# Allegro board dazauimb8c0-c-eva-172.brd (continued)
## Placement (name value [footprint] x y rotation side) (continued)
R242  0_5%_2  [R0201]  64.5 45.96 180 top
R243  75K_1%_2  [R0201]  61.28 45.83 0 top
R244  *EV@10K_5%_4  [R0402]  63.05 45.45 0 top
R245  EV@100K_5%_4  [R0402]  65.97 45.4 0 top
R246  TPC@0_5%_2  [R0201]  20.25 45.33 90 top
R247  TPC@0_5%_2  [R0201]  21.52 45.33 90 top
R248  4.7K_5%_2  [R0201]  213.57 45.27 90 top
R249  *10K_5%_4  [R0402]  215.38 45.22 180 top
R250  *10K_1%_2  [R0201]  78.37 45 0 top
R251  TPC_N@0_5%_2  [R0201]  20.25 44.87 270 top
R252  TPC_N@0_5%_2  [R0201]  21.52 44.87 270 top
R253  *10K_5%_2  [R0201]  60.69 44.87 90 top
R254  0_5%_2  [R0201]  63.43 44.54 180 top
R255  *1K_5%_2  [R0201]  81.72 44.06 90 top
R256  *10K_5%_2  [R0201]  78.04 43.93 180 top
R257  2.2K_5%_2  [R0201]  213.57 43.93 0 top
R258  *10K_1%_2  [R0201]  62.11 43.67 90 top
R259  200_1%_2  [R0201]  80.96 43.67 90 top
R260  2.2K_5%_2  [R0201]  213.57 42.91 0 top
R261  EV@10K_5%_4  [R0402]  62.14 42.23 90 top
R262  *EV@10K_5%_4  [R0402]  66.36 42.2 270 top
R263  *0_5%_4  [R0402]  97.06 42.02 0 top
R264  0_5%_4  [R0402]  30.54 41.9 90 top
R265  *0_5%_2  [R0201]  107.66 41.85 180 top
R266  *100K_5%_2  [R0201]  65.8 40.93 180 top
R267  *0_5%_4  [R0402]  30.16 40.5 180 top
R268  0_5%_4  [R0402]  97.98 40.25 180 top
R269  *100K_5%_2  [R0201]  65.21 40.12 180 top
R270  0_5%_2  [R0201]  61.78 39.48 270 top
R271  0_5%_2  [R0201]  62.55 39.48 270 top
R272  10K_5%_2  [R0201]  65.21 39.36 0 top
R273  *0_5%_4  [R0402]  97.34 39.23 0 top
R274  0_5%_8  [R0805]  101.66 39.03 90 top
R275  *0_5%_4  [R0402]  210.63 38.85 180 top
R276  10K_5%_2  [R0201]  65.21 38.59 0 top
R277  *100K_1%_2  [R0201]  93.2 38.29 0 top
R278  470_1%_2  [R0201]  66.36 38.09 0 top
R279  0_5%_4  [R0402]  97.09 38.09 0 top
R280  *Short_0402  [S0402]  22.67 37.96 180 top
R281  *short_4  [S0402]  210.63 37.83 180 top
R282  0_5%_2  [R0201]  66.48 37.2 270 top
R283  0_5%_4  [R0402]  97.1 37.11 0 top
R284  *Short_0402  [S0402]  22.67 36.94 180 top
R285  113_1%_2  [R0201]  95.69 36.56 180 top
R286  10K_5%_2  [R0201]  100.52 36.5 90 top
R287  10K_5%_2  [R0201]  93.23 36.44 180 top
R288  *0_5%_2  [R0201]  107.12 36.31 180 top
R289  *0_5%_4  [R0402]  210.75 35.8 180 top
R290  *20K_1%_2  [R0201]  90.49 35.72 90 top
R291  100K_5%_2  [R0201]  66.38 34.53 0 top
R292  100_1%_2  [R0201]  100.52 35.36 90 top
R293  *Short_0402  [S0402]  22.03 35.17 180 top
R294  240_1%_2  [R0201]  39.85 34.91 180 top
R295  0_5%_4  [R0402]  41.46 34.91 180 top
R296  49.9_1%_2  [R0201]  96.33 34.78 180 top
R297  *0_5%_2  [R0201]  107 34.73 270 top
R298  *Short_0402  [S0402]  22.03 34.15 180 top
R299  10K_5%_2  [R0201]  92.87 34.02 180 top
R300  1K_5%_2  [R0201]  93.91 34.02 0 top
R301  20K_1%_2  [R0201]  97.09 34.02 0 top
R302  75K_1%_2  [R0201]  87.06 33.64 180 top
R303  *20K_1%_2  [R0201]  88.43 33.44 90 top
R304  *4.7K_5%_2  [R0201]  97.09 33.26 180 top
R305  *Short_0402  [S0402]  22.16 33.13 180 top
R306  10K_5%_4  [R0402]  93.15 33.01 0 top
R307  22_1%_2  [R0201]  86.24 32.75 270 top
R308  60.4_1%_2  [R0201]  95.44 32.63 180 top
R309  *10K_1%_2  [R0201]  182.69 32.37 0 top
R310  33_5%_2  [R0201]  183.7 32.37 0 top
R311  75K_1%_2  [R0201]  85.53 32.32 270 top
R312  22_1%_4  [R0402]  158.99 32.32 0 top
R313  256@0_5%_4  [R0402]  213.12 32.29 0 top
R314  4.7K_5%_2  [R0201]  189.98 32.24 90 top
R315  4.7K_5%_2  [R0201]  190.71 32.24 90 top
R316  *Short_0402  [S0402]  22.16 32.12 180 top
R317  10K_5%_2  [R0201]  66.36 32.14 180 top
R318  33_5%_2  [R0201]  197.06 32.12 90 top
R319  75_1%_4  [R0402]  192.31 31.86 90 top
R320  75_1%_4  [R0402]  193.28 31.86 90 top
R321  75_1%_4  [R0402]  194.24 31.86 90 top
R322  0_5%_4  [R0402]  195.21 31.86 90 top
R323  22_1%_4  [R0402]  161.22 31.61 180 top
R324  100K_1%_4  [R0402]  162.98 31.61 0 top
R325  *10K_1%_2  [R0201]  181.42 31.53 90 top
R326  200_1%_2  [R0201]  84.77 31.48 270 top
R327  *10K_1%_2  [R0201]  94.3 31.36 0 top
R328  *4.7K_5%_2  [R0201]  85.84 31.33 90 top
R329  22_1%_2  [R0201]  87.11 31.3 270 top
R330  *10K_5%_2  [R0201]  66.31 30.92 180 top
R331  *0_5%_4  [R0402]  179.11 31.2 90 top
R332  *22_5%_8  [R0805]  51.4 31.13 90 top
R333  10K_1%_2  [R0201]  180.12 31.1 180 top
R334  20K_1%_2  [R0201]  89.77 30.8 180 top
R335  22_1%_4  [R0402]  161.99 30.59 0 top
R336  *short_4  [S0402]  167.45 30.59 180 top
R337  *20K_1%_2  [R0201]  86.68 30.39 180 top
R338  *256@0_5%_4  [R0402]  208.67 30.24 90 top
R339  100K_5%_2  [R0201]  66 29.15 0 top
R340  EV@4.7K_5%_2  [R0201]  171.36 30.19 0 top
R341  EV@4.7K_5%_2  [R0201]  173.11 30.19 180 top
R342  10K_5%_4  [R0402]  84.82 30.11 90 top
R343  100K_5%_4  [R0402]  95.57 29.96 0 top
R344  *short_4  [S0402]  180.15 29.83 270 top
R345  *short_4  [S0402]  202.02 29.83 135 top
R346  4.7K_5%_2  [R0201]  89.47 29.81 90 top
R347  *4.7K_5%_2  [R0201]  90.18 29.81 90 top
R348  100K_5%_2  [R0201]  181.04 29.73 270 top
R349  0_5%_2  [R0201]  146.11 29.7 270 top
R350  CNV@75K_1%_2  [R0201]  147.22 29.7 0 top
R351  100K_1%_4  [R0402]  164.15 29.65 0 top
R352  *866_1%_4  [R0402]  49.46 29.45 180 top
R353  *4.7K_5%_2  [R0201]  86.93 29.45 90 top
R354  43_5%_2  [R0201]  179.11 29.3 90 top
R355  *10K_5%_4  [R0402]  210.65 29.3 180 top
R356  2.2K_5%_2  [R0201]  91.78 29.27 180 top
R357  2.2K_5%_2  [R0201]  92.77 29.27 0 top
R358  0_5%_6  [R0603]  161.96 29.15 180 top
R359  100K_5%_2  [R0201]  65.75 28.41 0 top
R360  256@100K_5%_4  [R0402]  200.72 28.99 90 top
R361  2.2K_5%_2  [R0201]  89.98 28.94 180 top
R362  10K_1%_2  [R0201]  170.98 28.89 0 top
R363  22_1%_4  [R0402]  164.15 28.69 0 top
R364  1K_5%_2  [R0201]  210.65 28.28 0 top
R365  1K_5%_2  [R0201]  173.92 28.26 180 top
R366  *255@0_5%_4  [R0402]  209.31 28.21 270 top
R367  2.2K_5%_2  [R0201]  89.98 28.18 180 top
R368  33_5%_2  [R0201]  180.91 28.18 270 top
R369  10K_5%_4  [R0402]  171.89 28.05 180 top
R370  10K_5%_4  [R0402]  175.83 27.93 180 top
R371  10K_5%_4  [R0402]  177.61 27.93 0 top
R372  0_5%_2  [R0201]  65.34 27.55 270 top
R373  *0_5%_4  [R0402]  202.63 27.52 90 top
R374  *short_4  [S0402]  204.96 27.52 90 top
R375  *Short_0402  [S0402]  206.36 27.37 180 top
R376  SP@10K_5%_4  [R0402]  87.18 27.16 0 top
R377  10K_5%_4  [R0402]  79.97 26.78 90 top
R378  10K_1%_2  [R0201]  92.62 26.48 270 top
R379  *0_5%_2  [R0201]  89.85 26.4 90 top
R380  0_5%_2  [R0201]  90.61 26.4 90 top
R381  0_5%_2  [R0201]  91.37 26.4 90 top
R382  22_1%_4  [R0402]  162.62 26.4 180 top
R383  *10K_5%_2  [R0201]  88.96 26.38 270 top
R384  0_5%_4  [R0402]  164.78 26.38 180 top
R385  SP@10K_5%_4  [R0402]  85.6 26.35 270 top
R386  *2M_1%_4  [R0402]  47.94 25.77 0 top
R387  *1M_5%_4  [R0402]  49.72 25.77 0 top
R388  EV@100K_1%_4  [R0402]  78.7 25.77 270 top
R389  SP@10K_5%_4  [R0402]  86.96 25.54 0 top
R390  10K_5%_4  [R0402]  81.98 25.26 90 top
R391  *10K_5%_4  [R0402]  82.94 25.26 90 top
R392  SP@10K_5%_4  [R0402]  83.91 25.26 90 top
R393  33_5%_2  [R0201]  202.12 25.16 90 top
R394  33_5%_2  [R0201]  79.67 24.88 90 top
R395  33_5%_2  [R0201]  80.38 24.88 90 top
R396  *CNV@75K_1%_2  [R0201]  146.96 24.88 0 top
R397  8.2K_1%_2  [R0201]  66.61 24.78 180 top
R398  *TPM@Short_0201  [S0201]  122.87 24.5 270 top
R399  100K_5%_4  [R0402]  175.88 24.24 90 top
R400  *TPM@Short_0201  [S0201]  121.35 23.99 270 top
R401  2.2_5%_6  [R0603]  174.66 23.86 90 top
R402  33_5%_2  [R0201]  203.9 23.79 270 top
R403  TPM@33_5%_2  [R0201]  120.41 23.61 0 top
R404  CNV@75K_1%_2  [R0201]  147.64 23.61 180 top
R405  *20K_1%_2  [R0201]  67.24 23.48 180 top
R406  200K_1%_2  [R0201]  68.24 23.48 0 top
R407  TPC@100K_5%_4  [R0402]  205.67 23.48 270 top
R408  *20K_1%_2  [R0201]  77.15 23.1 0 top
R409  IV@1K/F_4  [R0402]  78.67 22.95 270 top
R410  33_5%_2  [R0201]  202.93 22.8 270 top
R411  TPM@10K_1%_2  [R0201]  120.66 22.69 270 top
R412  *TPM@Short_0201  [S0201]  121.4 22.69 270 top
R413  *4.7K_5%_2  [R0201]  67.88 22.59 90 top
R414  10K_5%_4  [R0402]  74.36 22.29 90 top
R415  *2.2K_5%_2  [R0201]  77.05 22.08 90 top
R416  *Short_0201  [S0201]  200.47 21.96 0 top
R417  TPM@33_5%_2  [R0201]  121.3 21.84 0 top
R418  PBA@10K_5%_4  [R0402]  51.9 21.83 270 top
R419  *22_5%_4  [R0402]  178.65 21.7 90 top
R420  *TPM@Short_0603  [S0603]  132.65 21.58 90 top
R421  TPC_N@100K_5%_4  [R0402]  204.35 21.58 270 top
R422  *Short_0402  [S0402]  47.31 21.32 180 top
R423  *TPM@1.2K_5%_2  [R0201]  130.34 20.56 180 top
R424  *10K_5%_4  [R0402]  70.65 20.46 180 top
R425  HDD_N@0_5%_2  [R0201]  209.1 20.38 90 top
R426  HDD_N@0_5%_2  [R0201]  210.37 20.38 90 top
R427  HDD_N@0_5%_2  [R0201]  211.14 20.38 90 top
R428  HDD_N@0_5%_2  [R0201]  212.51 20.38 90 top
R429  4.7K_5%_2  [R0201]  72.45 19.93 0 top
R430  33_5%_2  [R0201]  149.54 19.93 90 top
R431  *GS@Short_0402  [S0402]  58.48 19.67 180 top
R432  *TPM@0_5%_6  [R0603]  132.27 19.54 180 top
R433  *Short_0402  [S0402]  70.65 19.44 180 top
R434  *10K_5%_4  [R0402]  74.74 19.04 0 top
R435  HDD_R@4.7K_5%_2  [R0201]  205.04 18.91 180 top
R436  *HDD_R@4.7K_5%_2  [R0201]  206.82 18.88 0 top
R437  *0_5%_4  [R0402]  70.65 18.48 0 top
R438  *PBA@0_5%_4  [R0402]  47.43 18.4 90 top
R439  *CNV@71.5K_1%_4  [R0402]  145.71 18.15 180 top
R440  100K_5%_4  [R0402]  177.61 18.15 90 top
R441  *Short_0201  [S0201]  179.87 18.15 0 top
R442  *Short_0603  [S0603]  114.54 17.97 270 top
R443  *Short_0603  [S0603]  116.01 17.97 270 top
R444  *Short_0603  [S0603]  117.44 17.97 270 top
R445  *Short_0603  [S0603]  118.86 17.97 270 top
R446  *HDD_R@4.7K_5%_2  [R0201]  206.82 17.77 0 top
R447  TPC@10K_1%_4  [R0402]  21.37 17.69 270 top
R448  TPM@10K_1%_2  [R0201]  121.42 17.66 0 top
R449  *Short_0402  [S0402]  74.97 17.64 90 top
R450  *0_5%_4  [R0402]  75.93 17.64 270 top
R451  HDD_R@4.7K_5%_2  [R0201]  204.53 17.64 180 top
R452  *TPM@0_5%_6  [R0603]  131.94 17.51 270 top
R453  *TPM@Short_0603  [S0603]  134.25 17.51 270 top
R454  *10K_1%_4  [R0402]  54.8 17.39 270 top
R455  0_5%_2  [R0201]  146.32 17.28 0 top
R456  *0_5%_2  [R0201]  55.69 17 270 top
R457  *Short_0201  [S0201]  56.45 17 270 top
R458  TPM@33_5%_2  [R0201]  121.42 16.95 0 top
R459  100K_5%_2  [R0201]  201.41 16.95 0 top
R460  HDD_R@4.7K_5%_2  [R0201]  206.82 16.75 0 top
R461  *HDD_R@4.7K_5%_2  [R0201]  204.53 16.67 180 top
R462  100K_5%_2  [R0201]  180.55 16.37 270 top
R463  ODD@10K_5%_4  [R0402]  127.05 16.29 0 top
R464  *short_4  [S0402]  69.15 16.24 90 top
R465  *HDD_R@4.7K_5%_2  [R0201]  204.53 15.71 180 top
R466  HDD_R@4.7K_5%_2  [R0201]  206.82 15.61 0 top
R467  *0_5%_2  [R0201]  57.21 15.23 270 top
R468  *GS@10K_1%_2  [R0201]  69.15 14.97 180 top
R469  4.7K_5%_2  [R0201]  72.6 14.77 0 top
R470  *HDD_R@4.7K_5%_2  [R0201]  204.53 14.74 180 top
R471  HDD_R@4.7K_5%_2  [R0201]  206.82 14.72 0 top
R472  TPC@422K_1%_4  [R0402]  15.4 14.34 90 top
R473  0_5%_2  [R0201]  57.34 14.34 0 top
R474  *100K_2  [R0201]  53.96 14.26 90 top
R475  *GS@Short_0201  [S0201]  69.15 14.21 180 top
R476  *HDD_R@4.7K_5%_2  [R0201]  204.53 13.78 180 top
R477  HDD_R@4.7K_5%_2  [R0201]  206.79 13.32 0 top
R478  TPC@10K_1%_4  [R0402]  26.22 13.03 90 top
R479  EV@10K_1%_4  [R0402]  200.47 12.94 180 top
R480  *EV@10K_1%_4  [R0402]  202.37 12.94 180 top
R481  HDD_R@4.7K_5%_2  [R0201]  204.53 12.81 180 top
R482  TPC@100K_1%_4  [R0402]  17.03 12.61 0 top
R483  *GS@10K_1%_2  [R0201]  65.47 12.56 90 top
R484  *GS@Short_0201  [S0201]  66.36 12.56 90 top
R485  *HDD_R@4.7K_5%_2  [R0201]  206.79 12.56 0 top
R486  *TPC@Short_0402  [S0402]  10.6 11.8 180 top
R487  33_5%_2  [R0201]  197.55 11.67 180 top
R488  *HDD_R@Short_0402  [S0402]  204.91 11.16 90 top
R489  *TPC@Short_0402  [S0402]  10.6 10.65 180 top
R490  TPC@100K_1%_4  [R0402]  16.7 10.15 90 top
R491  *SSD@0_5%_2  [R0201]  22.29 9.26 0 top
R492  SSD@100K_1%_4  [R0402]  22.29 8.24 180 top
R493  TPC@470_1%_6  [R0603]  12.33 8.06 0 top
R494  TPC@10K_1%_4  [R0402]  14.13 7.78 90 top
R495  *SSD@Short_0201  [S0201]  26.73 6.59 180 top
R496  100K_1%_4  [R0402]  15.43 5.96 0 top
R497  *SSD@Short_0201  [S0201]  28.76 3.54 0 top
R498  *SSD@Short_0201  [S0201]  31.43 3.54 0 top
R499  *short_4  [S0402]  13.02 3.42 0 top
R500  *SSD@Short_0805  [S0805]  24.95 3.03 180 top
R501  *SSD@100K_5%_4  [R0402]  31.43 2.65 180 top
R502  *short_4  [S0402]  102.25 125.49 0 bottom
R503  EV@100K_1%_4  [R0402]  100.26 124.32 180 bottom
R504  EV@100K_1%_4  [R0402]  102.78 124.14 90 bottom
R505  *EV@Short_0402  [S0402]  104.33 123.43 180 bottom
R506  *EV@Short_0402  [S0402]  100.26 123.3 0 bottom
R507  2.2_5%_6  [R0603]  42.86 121.02 0 bottom
R508  EV@10K_1%_4  [R0402]  95.06 119.24 180 bottom
R509  *EV@Short_0402  [S0402]  100.77 119.24 180 bottom
R510  *EV@0_5%_4  [R0402]  100.77 118.22 180 bottom
R511  EV@2.49K_1%_2  [R0201]  116.65 118.06 270 bottom
R512  *EV@200_1%_2  [R0201]  115.25 117.84 180 bottom
R513  EV@10K_1%_4  [R0402]  103.34 117.82 180 bottom
R514  *Short_0402  [S0402]  40.07 115.68 180 bottom
R515  *Short_0805  [S0805]  67.63 108.77 90 bottom
R516  33_5%_2  [R0201]  58.05 105.17 90 bottom
R517  33_5%_2  [R0201]  56.2 105.04 180 bottom
R518  *Short_0603  [S0603]  59.12 104.76 270 bottom
R519  *Short_0402  [S0402]  44.13 103.62 90 bottom
R520  *Short_0402  [S0402]  45.15 103.62 90 bottom
R521  *Short_0402  [S0402]  46.16 103.62 90 bottom
R522  *Short_0402  [S0402]  47.18 103.62 90 bottom
R523  EV@120_1%_2  [R0201]  132.56 102.35 0 bottom
R524  EV@80.6_1%_2  [R0201]  134.17 102.35 180 bottom
R525  EV@10K_1%_4  [R0402]  119.31 100.82 270 bottom
R526  EV@10K_1%_4  [R0402]  119.31 98.92 270 bottom
R527  EV@10K_1%_4  [R0402]  121.22 98.92 0 bottom
R528  EV@10K_1%_4  [R0402]  90.49 98.16 0 bottom
R529  *EV@100K_5%_4  [R0402]  88.2 97.65 0 bottom
R530  EV@120_1%_2  [R0201]  132.78 97.48 270 bottom
R531  EV@80.6_1%_2  [R0201]  134.94 97.27 180 bottom
R532  EV@100K_5%_4  [R0402]  90.49 97.14 180 bottom
R533  EV@100K_5%_4  [R0402]  88.2 96.63 0 bottom
R534  EV@100K_5%_4  [R0402]  90.49 96.13 180 bottom
R535  100K_1%_2  [R0201]  81 96.02 0 bottom
R536  *short_4  [S0402]  82.61 96.02 180 bottom
R537  EV@10K_1%_4  [R0402]  85.13 95.77 270 bottom
R538  EV@100K_5%_4  [R0402]  88.2 95.62 0 bottom
R539  EV@100K_5%_4  [R0402]  90.49 94.98 0 bottom
R540  *EV@100K_5%_4  [R0402]  88.2 94.6 0 bottom
R541  EV@60.4_1%_2  [R0201]  120.48 94.47 0 bottom
R542  *EV@0_5%_4  [R0402]  85.13 94.09 0 bottom
R543  EV@100K_5%_4  [R0402]  90.49 93.97 180 bottom
R544  EV@100K_5%_4  [R0402]  88.2 93.59 0 bottom
R545  EV@100K_5%_4  [R0402]  90.49 92.95 180 bottom
R546  *EV@100K_5%_4  [R0402]  88.2 92.57 0 bottom
R547  EV@100K_5%_4  [R0402]  90.49 91.93 180 bottom
R548  EV@10K_1%_4  [R0402]  88.2 91.55 0 bottom
R549  *EV@Short_0402  [S0402]  90.23 90.92 180 bottom
R550  EV@10K_1%_4  [R0402]  87.95 90.56 0 bottom
R551  *EV@Short_0402  [S0402]  90.23 89.95 180 bottom
R552  EV@100K_5%_4  [R0402]  103.69 89.78 180 bottom
R553  *EV@30.1K_1%_4  [R0402]  105.47 89.78 0 bottom
R554  *EV@100K_5%_4  [R0402]  107.25 89.78 180 bottom
R555  *EV@10K_1%_4  [R0402]  88.2 89.52 0 bottom
R556  EV@10K_5%_4  [R0402]  91.6 89.01 90 bottom
R557  *EV@10K_5%_4  [R0402]  92.57 89.01 90 bottom
R558  EV@2.2K_5%_2  [R0201]  93.53 89.01 270 bottom
R559  EV@2.2K_5%_2  [R0201]  94.5 89.01 270 bottom
R560  EV@2.2K_5%_2  [R0201]  95.46 89.01 270 bottom
R561  EV@2.2K_5%_2  [R0201]  96.43 89.01 270 bottom
R562  *EV@10K_1%_4  [R0402]  97.39 89.01 90 bottom
R563  EV@10K_1%_4  [R0402]  98.36 89.01 90 bottom
R564  EV@10K_1%_4  [R0402]  90.23 88.99 0 bottom
R565  EV@100K_5%_4  [R0402]  103.69 88.81 0 bottom
R566  EV@100K_5%_4  [R0402]  105.47 88.81 180 bottom
R567  EV@100K_5%_4  [R0402]  107.25 88.81 180 bottom
R568  *EV@Short_0402  [S0402]  108.98 88.81 180 bottom
R569  *EV@Short_0402  [S0402]  96.12 87.36 0 bottom
R570  EV@10K_1%_4  [R0402]  97.85 87.36 0 bottom
R571  *0_5%_2  [R0201]  105.24 86.55 180 bottom
R572  *10K_5%_2  [R0201]  92.04 86.3 90 bottom
R573  *10K_5%_2  [R0201]  88.61 86.09 90 bottom
R574  *10K_5%_2  [R0201]  92.9 85.84 0 bottom
R575  100_1%_2  [R0201]  72.01 85.48 270 bottom
R576  100_1%_2  [R0201]  72.77 85.48 270 bottom
R577  100_1%_2  [R0201]  73.51 85.48 270 bottom
R578  *0_5%_2  [R0201]  92.39 84.9 90 bottom
R579  100_1%_2  [R0201]  93.66 84.9 270 bottom
R580  10K_5%_2  [R0201]  94.4 84.9 90 bottom
R581  *100K_5%_2  [R0201]  95.16 84.9 270 bottom
R582  1K_1%_2  [R0201]  99.43 84.57 270 bottom
R583  499_1%_2  [R0201]  98.51 84.39 180 bottom
R584  1K_1%_2  [R0201]  102.78 83.15 0 bottom
R585  100_1%_2  [R0201]  104.18 83.04 90 bottom
R586  0_5%_2  [R0201]  101.28 82.26 0 bottom
R587  0_5%_2  [R0201]  101.28 81.49 0 bottom
R588  56_1%_2  [R0201]  102.8 81.44 0 bottom
R589  *150_1%_4  [R0402]  14.16 80.76 90 bottom
R590  0_5%_2  [R0201]  101.28 80.68 0 bottom
R591  49.9_1%_2  [R0201]  102.8 80.38 0 bottom
R592  0_5%_2  [R0201]  102.8 79.67 180 bottom
R593  100K_1%_2  [R0201]  101.28 79.62 0 bottom
R594  *51_1%_2  [R0201]  102.81 78.79 0 bottom
R595  *150_1%_4  [R0402]  14.16 78.73 90 bottom
R596  0_5%_6  [R0603]  104.36 78.38 270 bottom
R597  100_1%_2  [R0201]  102.8 78.07 0 bottom
R598  0_5%_2  [R0201]  101.81 77.71 270 bottom
R599  100_1%_2  [R0201]  102.8 77.33 0 bottom
R600  *51_1%_2  [R0201]  101.08 77.08 90 bottom
R601  *150_1%_4  [R0402]  14.16 76.82 90 bottom
R602  0_5%_2  [R0201]  101.81 76.69 270 bottom
R603  51_1%_2  [R0201]  102.8 75.93 0 bottom
R604  0_5%_2  [R0201]  101.28 75.81 0 bottom
R605  *0_5%_4  [R0402]  60.77 75.04 90 bottom
R606  *150_1%_4  [R0402]  14.16 74.92 90 bottom
R607  *51_1%_2  [R0201]  103.31 74.61 90 bottom
R608  0_5%_2  [R0201]  104.05 74.15 270 bottom
R609  *Short_0402  [S0402]  60.77 73.27 90 bottom
R610  150_1%_2  [R0201]  102.55 73.01 270 bottom
R611  *22_5%_8  [R0805]  106.82 68.26 180 bottom
R612  *2M_1%_4  [R0402]  112.46 68.19 180 bottom
R613  *1M_5%_4  [R0402]  112.46 67.17 0 bottom
R614  866_1%_2  [R0201]  109.21 65.82 270 bottom
R615  240_1%_2  [R0201]  60.64 63.23 180 bottom
R616  *0_5%_6  [R0603]  107.5 62.6 180 bottom
R617  150_1%_2  [R0201]  101.15 62.5 270 bottom
R618  *2M_1%_4  [R0402]  114.11 62.34 270 bottom
R619  *Short_0603  [S0603]  110.3 62.19 180 bottom
R620  *47_5%_8  [R0805]  110.98 59.8 90 bottom
R621  *10K_1%_4  [R0402]  113.14 58 180 bottom
R622  0_5%_2  [R0201]  19.62 57.26 180 bottom
R623  0_5%_6  [R0603]  102.04 57.26 0 bottom
R624  *1M_5%_4  [R0402]  110.04 56.25 90 bottom
R625  866_1%_2  [R0201]  111.06 56.25 270 bottom
R626  *Short_0402  [S0402]  103.24 55.87 0 bottom
R627  *0_5%_2  [R0201]  110.83 54.72 0 bottom
R628  *100K_2  [R0201]  113.98 54.57 0 bottom
R629  TPM@10K_5%_4  [R0402]  61.02 54.09 0 bottom
R630  TPM_N@10K_5%_4  [R0402]  62.93 54.09 0 bottom
R631  HDMI_R@10K_5%_4  [R0402]  61.02 53.12 0 bottom
R632  HDMI_N@10K_5%_4  [R0402]  62.93 53.12 0 bottom
R633  *1K_1%_2  [R0201]  101.49 52.04 180 bottom
R634  GS@10K_5%_4  [R0402]  61.02 52.03 0 bottom
R635  GS_N@10K_5%_4  [R0402]  62.93 52.03 0 bottom
R636  *short_4  [S0402]  105.6 51.93 0 bottom
R637  60.4_1%_2  [R0201]  101.29 51.33 180 bottom
R638  1K_1%_2  [R0201]  102.58 52.11 0 bottom
R639  *10K_5%_4  [R0402]  61.02 51.07 0 bottom
R640  10K_5%_4  [R0402]  62.93 51.07 0 bottom
R641  *0_5%_4  [R0402]  105.34 50.91 0 bottom
R642  *0_5%_4  [R0402]  107.12 50.91 0 bottom
R643  *10K_5%_2  [R0201]  101.05 50.43 90 bottom
R644  TPC@10K_5%_4  [R0402]  61.02 49.97 0 bottom
R645  TPC_N@10K_5%_4  [R0402]  63.05 49.97 0 bottom
R646  TPC_N@0_5%_8  [R0805]  17.59 49.14 90 bottom
R647  DMIC@10K_5%_4  [R0402]  61.02 49.01 0 bottom
R648  *10K_5%_4  [R0402]  62.93 49.01 0 bottom
R649  TPC_N@0_5%_8  [R0805]  21.78 48.88 90 bottom
R650  10K_5%_4  [R0402]  61.02 48.04 0 bottom
R651  *10K_5%_4  [R0402]  62.44 47.56 270 bottom
R652  *10K_5%_4  [R0402]  61.02 47.08 0 bottom
R653  10K_5%_4  [R0402]  63.05 46.21 0 bottom
R654  100K_1%_2  [R0201]  61.02 46.11 180 bottom
R655  *4.7K_5%_2  [R0201]  60.51 45.12 90 bottom
R656  *20K_1%_2  [R0201]  61.28 45.12 270 bottom
R657  *10K_5%_2  [R0201]  62.55 45.12 270 bottom
R658  *EV@10K_1%_2  [R0201]  60.49 44.13 270 bottom
R659  10K_5%_2  [R0201]  62.09 44.13 0 bottom
R660  *100K_5%_2  [R0201]  108.11 43.45 270 bottom
R661  *100K_5%_2  [R0201]  108.88 43.45 270 bottom
R662  100K_5%_2  [R0201]  63.94 43.42 90 bottom
R663  *4.7K_5%_2  [R0201]  66.1 43.29 0 bottom
R664  *4.7K_5%_2  [R0201]  60.64 43.27 0 bottom
R665  *20K_1%_2  [R0201]  62.16 43.27 0 bottom
R666  *20K_1%_2  [R0201]  67.12 43.22 0 bottom
R667  *100K_2  [R0201]  110.86 42.4 90 bottom
R668  0_5%_2  [R0201]  108.66 42.33 270 bottom
R669  0_5%_2  [R0201]  109.38 42.33 270 bottom
R670  100K_2  [R0201]  110.11 42.33 270 bottom
R671  10K_5%_2  [R0201]  64.45 42.02 270 bottom
R672  *75K_1%_2  [R0201]  66.23 41.77 270 bottom
R673  *EV@10K_5%_4  [R0402]  60.79 41.64 90 bottom
R674  *0_5%_2  [R0201]  111.97 41.57 0 bottom
R675  *0_5%_2  [R0201]  110.96 40.85 0 bottom
R676  *0_5%_2  [R0201]  111.97 40.85 0 bottom
R677  *4.7K_5%_2  [R0201]  65.72 40.5 270 bottom
R678  10K_5%_2  [R0201]  63.31 40.37 90 bottom
R679  1K_5%_2  [R0201]  64.83 40.25 0 bottom
R680  *0_5%_2  [R0201]  110.96 40.14 0 bottom
R681  *100K_2  [R0201]  111.97 40.14 180 bottom
R682  33_5%_2  [R0201]  66.1 39.61 0 bottom
R683  33_5%_2  [R0201]  64.83 39.48 0 bottom
R684  33_5%_2  [R0201]  66.1 38.85 0 bottom
R685  100K_5%_2  [R0201]  67.12 38.85 180 bottom
R686  100K_5%_4  [R0402]  203.16 38.37 90 bottom
R687  33_5%_2  [R0201]  65.47 38.11 0 bottom
R688  *100K_2  [R0201]  108.27 38.09 270 bottom
R689  0_5%_2  [R0201]  67.37 36.82 90 bottom
R690  255@0_5%_4  [R0402]  211.54 36.44 90 bottom
R691  *0_5%_4  [R0402]  198.23 35.98 0 bottom
R692  0_5%_2  [R0201]  67.37 35.8 270 bottom
R693  10M_5%_2  [R0201]  66.41 35.7 270 bottom
R694  256@0_5%_4  [R0402]  196.3 35.6 0 bottom
R695  *short_6  [S0603]  198.49 34.73 0 bottom
R696  0_5%_2  [R0201]  66.41 34.66 270 bottom
R697  255@0_5%_4  [R0402]  196.3 34.53 0 bottom
R698  *10K_1%_2  [R0201]  192.16 34.28 270 bottom
R699  *Short_0201  [S0201]  195.95 33.62 0 bottom
R700  *10K_1%_2  [R0201]  192.04 33.29 90 bottom
R701  100K_5%_2  [R0201]  66.23 33.23 0 bottom
R702  *0_5%_2  [R0201]  63.94 32.63 270 bottom
R703  0_5%_2  [R0201]  64.73 32.63 270 bottom
R704  1K_5%_2  [R0201]  66.74 32.37 0 bottom
R705  *4.7K_5%_2  [R0201]  69.78 32.37 0 bottom
R706  100K_5%_2  [R0201]  71.05 32.37 180 bottom
R707  22K_5%_4  [R0402]  196.02 32.24 270 bottom
R708  *100K_5%_2  [R0201]  68.64 32.12 180 bottom
R709  100K_5%_2  [R0201]  66.74 31.61 0 bottom
R710  0_5%_6  [R0603]  102.17 31.43 180 bottom
R711  0_5%_2  [R0201]  68.64 31.36 180 bottom
R712  *1M_5%_2  [R0201]  69.78 31.36 90 bottom
R713  10K_5%_2  [R0201]  71.31 31.36 270 bottom
R714  *100K_2  [R0201]  108.88 30.85 0 bottom
R715  200K_1%_4  [R0402]  199.43 30.72 0 bottom
R716  *1M_5%_2  [R0201]  66.86 30.59 180 bottom
R717  *0_5%_2  [R0201]  67.88 30.59 180 bottom
R718  10K_1%_2  [R0201]  196 30.34 90 bottom
R719  0_5%_6  [R0603]  104.25 30.06 90 bottom
R720  *0_5%_4  [R0402]  198.03 29.7 90 bottom
R721  100K_5%_2  [R0201]  78.17 29.63 180 bottom
R722  *4.7K_5%_2  [R0201]  79.16 29.63 0 bottom
R723  0_5%_2  [R0201]  76.64 29.6 180 bottom
R724  150_1%_2  [R0201]  74.99 29.58 180 bottom
R725  *20K_1%_2  [R0201]  89.72 29.58 180 bottom
R726  0_5%_2  [R0201]  97.98 29.51 180 bottom
R727  0_5%_2  [R0201]  99 29.51 0 bottom
R728  100K_5%_2  [R0201]  88.33 29.48 180 bottom
R729  *10K_5%_4  [R0402]  81.14 29.07 90 bottom
R730  SP@10K_5%_4  [R0402]  82.1 29.07 270 bottom
R731  SP@10K_5%_4  [R0402]  83.12 29.07 90 bottom
R732  SP@10K_5%_4  [R0402]  84.14 29.07 270 bottom
R733  10K_5%_2  [R0201]  87.31 29.23 270 bottom
R734  255@100K_5%_4  [R0402]  200.7 29.04 90 bottom
R735  *20K_1%_2  [R0201]  89.72 28.82 0 bottom
R736  *4.7K_5%_2  [R0201]  95.6 28.82 0 bottom
R737  *10K_5%_4  [R0402]  96.58 28.82 90 bottom
R738  *CNV_N@0_5%_8  [R0805]  193.99 28.82 180 bottom
R739  *20K_1%_2  [R0201]  88.33 28.76 180 bottom
R740  200K_1%_2  [R0201]  98.61 28.69 180 bottom
R741  *10K_1%_2  [R0201]  94.03 28.51 270 bottom
R742  *10K_1%_2  [R0201]  94.74 28.51 270 bottom
R743  *4.7K_5%_2  [R0201]  76.64 28.43 0 bottom
R744  22_1%_4  [R0402]  78.17 28.38 0 bottom
R745  *Short_0402  [S0402]  208.01 28.13 90 bottom
R746  256@0_5%_4  [R0402]  198.74 28.08 0 bottom
R747  20K_1%_2  [R0201]  89.72 28.05 0 bottom
R748  *Short_0402  [S0402]  91.25 28.05 180 bottom
R749  22_5%_2  [R0201]  206.79 27.82 90 bottom
R750  20K_1%_2  [R0201]  88.45 27.8 90 bottom
R751  33_5%_2  [R0201]  203.26 27.65 270 bottom
R752  *100K_5%_4  [R0402]  205.93 27.55 90 bottom
R753  100K_5%_2  [R0201]  76.64 27.29 0 bottom
R754  256@0_5%_4  [R0402]  201.26 27.27 90 bottom
R755  0_5%_2  [R0201]  77.66 27.16 180 bottom
R756  256@3.3K_5%_2  [R0201]  198.44 27.16 180 bottom
R757  *49.9K_1%_2  [R0201]  85.63 27.04 270 bottom
R758  *49.9K_1%_2  [R0201]  86.93 27.04 180 bottom
R759  22_1%_4  [R0402]  78.65 26.91 270 bottom
R760  100K_5%_2  [R0201]  96.58 26.91 270 bottom
R761  CNV@22_1%_2  [R0201]  196.45 26.76 90 bottom
R762  100K_5%_2  [R0201]  81.21 26.66 270 bottom
R763  SP@10K_5%_4  [R0402]  82.61 26.66 180 bottom
R764  *0_5%_4  [R0402]  93.79 26.66 90 bottom
R765  *20K_1%_2  [R0201]  94.68 26.53 90 bottom
R766  *TPC@4.7K_5%_2  [R0201]  91.37 26.43 270 bottom
R767  *20K_1%_2  [R0201]  92.14 26.43 270 bottom
R768  10K_5%_2  [R0201]  92.85 26.43 90 bottom
R769  *CNV@Short_0805  [S0805]  193.86 26.43 180 bottom
R770  *Short_0402  [S0402]  67.09 26.4 270 bottom
R771  100K_5%_2  [R0201]  77.1 26.12 180 bottom
R772  256@3.3K_5%_2  [R0201]  198.64 26.1 180 bottom
R773  *TPC@Short_0603  [S0603]  20.99 26.05 90 bottom
R774  *TPC@4.7K_5%_2  [R0201]  16.34 25.79 270 bottom
R775  *TPC@4.7K_5%_2  [R0201]  19.75 25.64 90 bottom
R776  0_5%_2  [R0201]  81.21 25.64 270 bottom
R777  22_1%_4  [R0402]  78.47 25.56 0 bottom
R778  *4.7K_5%_2  [R0201]  76.39 25.39 180 bottom
R779  2.2K_5%_2  [R0201]  86.12 25.39 90 bottom
R780  *Short_0603  [S0603]  211.15 25.34 0 bottom
R781  TPC@4.7K_5%_2  [R0201]  15.58 25.26 90 bottom
R782  255@0_5%_4  [R0402]  199.05 24.78 90 bottom
R783  100K_1%_2  [R0201]  78.64 24.6 0 bottom
R784  4.7K_5%_2  [R0201]  75.47 24.55 90 bottom
R785  *TPC@4.7K_5%_2  [R0201]  20.13 24.24 180 bottom
R786  100K_5%_2  [R0201]  194.96 23.76 90 bottom
R787  4.7K_5%_2  [R0201]  75.32 23.68 0 bottom
R788  4.7K_5%_2  [R0201]  81.98 23.61 180 bottom
R789  *100K_5%_2  [R0201]  78.8 23.4 0 bottom
R790  *0_5%_2  [R0201]  86.12 23.23 270 bottom
R791  10K_1%_2  [R0201]  198.31 23.23 90 bottom
R792  *0_5%_2  [R0201]  82.87 22.97 90 bottom
R793  CNV@22_1%_2  [R0201]  193.53 22.95 0 bottom
R794  *2.2_5%_6  [R0603]  178.37 22.9 180 bottom
R795  *10K_5%_4  [R0402]  68.26 22.34 90 bottom
R796  *short_4  [S0402]  69.28 22.34 270 bottom
R797  *10K_5%_4  [R0402]  70.29 22.34 270 bottom
R798  *short_4  [S0402]  71.26 22.34 90 bottom
R799  *CNV@20K_1%_2  [R0201]  195.16 22.34 90 bottom
R800  4.7K_5%_2  [R0201]  86.12 22.19 270 bottom
R801  2.2K_5%_2  [R0201]  82.87 21.96 270 bottom
R802  *Short_0402  [S0402]  193.53 21.78 180 bottom
R803  2.2_5%_6  [R0603]  178.37 21.47 180 bottom
R804  *short_4  [S0402]  53.91 20.97 180 bottom
R805  4.7K_5%_2  [R0201]  193.2 20.76 180 bottom
R806  *ODD@10K_5%_4  [R0402]  139.51 20.69 270 bottom
R807  *Short_0402  [S0402]  64.65 20.23 180 bottom
R808  TPC@4.7K_5%_2  [R0201]  24.19 20.18 270 bottom
R809  *TPC@4.7K_5%_4  [R0402]  25.16 20.18 90 bottom
R810  *ODD@Short_0805  [S0805]  123.3 20.05 180 bottom
R811  4.7K_5%_2  [R0201]  193.2 20.05 180 bottom
R812  ODD@33_5%_2  [R0201]  140.52 19.93 270 bottom
R813  *short_4  [S0402]  19.75 19.8 0 bottom
R814  *TPC@100K_1%_4  [R0402]  26.55 19.8 90 bottom
R815  TPC@100K_1%_2  [R0201]  27.52 19.8 270 bottom
R816  10K_5%_2  [R0201]  181.47 19.8 90 bottom
R817  *TPC@4.7K_5%_2  [R0201]  16.95 19.67 180 bottom
R818  *TPC@0_5%_6  [R0603]  12.58 19.59 0 bottom
R819  *Short_0201  [S0201]  193.36 19.34 0 bottom
R820  *short_4  [S0402]  64.65 19.21 180 bottom
R821  TPC@100K_1%_2  [R0201]  22.16 19.01 0 bottom
R822  *TPC@4.7K_5%_2  [R0201]  19.49 18.78 270 bottom
R823  *TPC@4.7K_5%_2  [R0201]  20.33 18.78 90 bottom
R824  *TPC@4.7K_5%_2  [R0201]  16.95 18.66 0 bottom
R825  *10K_1%_2  [R0201]  193.1 18.48 0 bottom
R826  TPC@100K_1%_2  [R0201]  27.75 18.02 270 bottom
R827  KBL@10K_5%_4  [R0402]  196.25 17.79 0 bottom
R828  *10K_1%_2  [R0201]  193.1 17.77 0 bottom
R829  TPC@100K_1%_2  [R0201]  21.7 17.72 0 bottom
R830  0_5%_2  [R0201]  193.28 16.95 180 bottom
R831  0_5%_2  [R0201]  193 16.22 180 bottom
R832  0_5%_2  [R0201]  192.72 15.1 180 bottom
R833  200K_1%_2  [R0201]  180.3 14.92 270 bottom
R834  GS_N@0_5%_2  [R0201]  211.75 14.92 180 bottom
R835  *Short_0201  [S0201]  211.62 14.21 180 bottom
R836  *Short_0402  [S0402]  193.61 13.58 0 bottom
R837  *Short_0201  [S0201]  211.75 13.47 180 bottom
R838  TPC@100K_1%_2  [R0201]  24.75 12.33 180 bottom
R839  TPC@100K_1%_2  [R0201]  23.28 12.13 270 bottom
R840  TPC@100K_1%_2  [R0201]  26.15 12.13 90 bottom
R841  45.3K_1%_4  [R0402]  17.84 11.67 0 bottom
R842  1.5K_5%_4  [R0402]  19.62 11.67 0 bottom
R843  *SSD@Short_0201  [S0201]  31.84 11.64 270 bottom
R844  *SSD@Short_0201  [S0201]  32.6 11.64 270 bottom
R845  *SSD@Short_0201  [S0201]  34.07 11.64 270 bottom
R846  *SSD@Short_0201  [S0201]  34.83 11.64 270 bottom
R847  *SSD@Short_0201  [S0201]  26.99 11.54 270 bottom
R848  *SSD@Short_0201  [S0201]  27.75 11.54 270 bottom
R849  *SSD@Short_0201  [S0201]  29.14 11.54 270 bottom
R850  *SSD@Short_0201  [S0201]  29.91 11.54 270 bottom
R851  *SSD@Short_0201  [S0201]  38.29 11.54 270 bottom
R852  *SSD@Short_0201  [S0201]  39.05 11.54 270 bottom
R853  20K_1%_2  [R0201]  15.17 10.81 180 bottom
R854  20K_1%_2  [R0201]  15.17 10.1 180 bottom
R855  1K/F_4  [R0402]  16.7 8.09 180 bottom
RV1  TPC@MESD3324PCR  [SON10-2_5X1-5-0_55H]  10.98 16.12 90 top
RV2  TPC@MESD3324PCR  [SON10-2_5X1-5-0_55H]  10.98 16.12 270 bottom
RV3  TPC@MESD05N92ULA  [DFN1006-3-1X0_6-0_55H-3P]  10.6 11.29 180 bottom
SW1  *T3AL-23S-Q-T/R  [SW-T3AL-23-Q-TR-4P]  171.26 24.5 90 top
SW2  RESET_SW  [SW-TME-532-V-6P]  64.85 100.9 270 bottom
SW3  *NDT016-G1A-KKKT  [SW-NDT016-G1A-KKKT-4P]  19.1 60.62 180 bottom
TP1  *TP  [TP2050]  69.96 117.05 0 top
TP2  *  [TP2050]  46.62 110.4 180 top
TP3  *  [TP2050]  47.06 109.21 180 top
TP4  *  [TP2050]  45.92 108.65 180 top
TP5  *  [TP2050]  102.2 96.63 0 top
TP6  *  [TP2050]  103.69 96 0 top
TP7  *  [TP2050]  70.04 94.86 270 top
TP8  *  [TP2050]  68.77 94.35 270 top
TP9  *  [TP2050]  86.04 93.13 0 top
TP10  *  [TP2050]  90.36 91.68 0 top
TP11  *  [TP2050]  107 89.14 0 top
TP12  *  [TP2050]  101.53 78.09 270 top
TP13  *  [TP2050]  94.12 77.3 270 top
TP14  *  [TP2050]  95.46 76.24 180 top
TP15  *  [TP2050]  97.62 76.06 180 top
TP16  *  [TP2050]  98.08 73.57 270 top
TP17  *  [TP2050]  103.69 73.01 0 top
TP18  *  [TP2050]  94.04 54.6 90 top
TP19  *  [TP2050]  91.86 52.64 270 top
TP20  *  [TP2050]  90.94 51.75 270 top
TP21  *  [TP2050]  82.1 46.85 270 top
TP22  *  [TP2050]  84.47 46.21 270 top
TP23  *  [TP2050]  82.23 45.58 270 top
TP24  *  [TP2050]  83.55 45.33 270 top
TP25  *  [TP2050]  80.94 45.25 270 top
TP26  *  [TP2050]  79.31 44.94 270 top
TP27  *  [TP2050]  82.51 44.33 270 top
TP28  *  [TP2050]  78.42 43.17 270 top
TP29  *  [TP2050]  78.95 41.13 270 top
TP30  *  [TP2050]  97.72 41.06 270 top
TP31  *  [TP2050]  77.15 40.09 0 top
TP32  *  [TP2050]  66.48 39.86 0 top
TP33  *  [TP2050]  94.3 36.38 270 top
TP34  *  [TP2050]  91.76 34.53 90 top
TP35  *TP  [TP2050]  185.76 31.36 0 top
TP36  *  [TP2050]  209.52 30.48 0 top
TP37  *  [TP2050]  83.12 30.21 0 top
TP38  *  [TP2050]  83.5 28.82 0 top
TP39  *TP  [TP2050]  181.85 27.72 0 top
TP40  *TP  [TP2050]  180.81 26.99 0 top
TP41  *  [TP2050]  209.71 26.96 0 top
TP42  *TP  [TP2050]  179.54 26.78 0 top
TP43  *TP  [TP2050]  200.72 24.88 0 top
TP44  *TP  [TP2050]  150.94 23.61 0 top
TP45  *PAD  [TP2050]  11.24 12.81 0 top
TP46  *TP  [TP2050]  189.93 12.69 0 top
TP47  *TP  [TP2050]  196.78 12.69 0 top
TP48  *TP  [TP2050]  187.51 10.4 0 top
TP49  *PAD  [TP2050]  17.64 4.84 0 top
TP50  *  [TP2050]  94.45 118.35 180 bottom
TP51  *  [TP2050]  95.72 118.35 180 bottom
TP52  *  [TP2050]  97.01 118.35 180 bottom
TP53  *  [TP2050]  98.61 118.35 180 bottom
TP54  *  [TP2050]  90.26 111.87 180 bottom
TP55  *  [TP2050]  90.1 110.6 180 bottom
TP56  *  [TP2050]  91.12 106.92 180 bottom
TP57  *  [TP2050]  91.12 105.4 180 bottom
TP58  *  [TP2050]  76.44 86.52 90 bottom
TP59  *TP  [TP2050]  68.13 85.97 180 bottom
TP60  *  [TP2050]  74.36 85.18 90 bottom
TP61  *  [TP2050]  88.86 85.1 90 bottom
TP62  *  [TP2050]  101.84 84.36 90 bottom
TP63  *  [TP2050]  89.88 84.34 90 bottom
TP64  *  [TP2050]  103.16 84.01 90 bottom
TP65  *  [TP2050]  101.81 83.09 90 bottom
TP66  *  [TP2050]  101.79 78.85 270 bottom
TP67  *  [TP2050]  104.08 76.76 270 bottom
TP68  *  [TP2050]  105.34 76.44 90 bottom
TP69  *  [TP2050]  104.38 75.47 90 bottom
TP70  *  [TP2050]  104.81 74.2 0 bottom
TP71  *  [TP2050]  103.82 73.01 90 bottom
TP72  *  [TP2050]  101 64.27 90 bottom
TP73  *  [TP2050]  102.3 64.25 90 bottom
TP74  *  [TP2050]  103.57 64.26 90 bottom
TP75  *  [TP2050]  102.98 63.13 90 bottom
TP76  *  [TP2050]  101.97 62.37 90 bottom
TP77  *  [TP2050]  103.31 61.89 90 bottom
TP78  *  [TP2050]  143.65 41.72 180 bottom
TP79  *  [TP2050]  67.37 37.96 270 bottom
TP80  *  [TP2050]  104.2 35.17 90 bottom
TP81  *  [TP2050]  103.06 34.53 90 bottom
TP82  *  [TP2050]  65.59 32.37 270 bottom
TP83  *PAD  [TP2050]  191.88 32.12 180 bottom
TP84  *  [TP2050]  103.26 29.55 90 bottom
TP85  *  [TP2050]  101.89 29.5 90 bottom
TP86  *  [TP2050]  86.37 29.3 270 bottom
TP87  *  [TP2050]  100.65 28.94 90 bottom
TP88  *  [TP2050]  102.96 28.31 90 bottom
TP89  *  [TP2050]  101.69 28.21 90 bottom
TP90  *  [TP2050]  86.32 27.88 270 bottom
TP91  *  [TP2050]  88.71 26.91 180 bottom
TP92  *  [TP2050]  76.21 26.5 270 bottom
TP93  *  [TP2050]  101.41 25.89 90 bottom
TP94  *  [TP2050]  82.1 25.64 180 bottom
TP95  *  [TP2050]  68.34 24.85 90 bottom
TP96  *  [TP2050]  76.77 24.55 90 bottom
TP97  *  [TP2050]  67.52 23.79 90 bottom
TP98  *PAD  [TP2050]  9.97 20.05 180 bottom
TP99  *PAD  [TP2050]  194.17 14.44 180 bottom
TP100  *PAD  [TP2050]  193.74 12.43 180 bottom
TP101  *PAD  [TP2050]  195.01 12.43 180 bottom
U1  RTL8111HSH-CG  [QFN32-4X4-4-33P-0_9H]  44.64 105.4 270 top
U2  DDR4_96P  [BGA96-MICRON-MT41J64M16JT-187EG]  40.27 87.83 270 top
U3  HDMI_R@PTN3366BS  [QFN32-5X5-5-37P-0_85H]  21.27 78.47 180 top
U4  DDR4_96P  [BGA96-MICRON-MT41J64M16JT-187EG]  40.27 74.53 270 top
U5  USB30_ESD_AZ1065-06F.R7G  [ESD10-4_1X2-8-11P]  17.97 55.49 90 top
U6  DDR4_96P  [BGA96-MICRON-MT41J64M16JT-187EG]  40.27 54.63 270 top
U7  TPC@SLGC55544VTR  [QFN16-3X3-5-17P-TPS2546RTER]  20.13 48.63 0 top
U8  DDR4_96P  [BGA96-MICRON-MT41J64M16JT-187EG]  40.27 41.48 270 top
U9  *74AUP1G32SE-7  [SC70-2_1-65-5P]  106.61 38.98 90 top
U10  *74AUP1G32SE-7  [SC70-2_1-65-5P]  109.92 36.82 90 top
U11  USB30_ESD_AZ1065-06F.R7G  [ESD10-4_1X2-8-11P]  18.73 34.78 90 top
U12  *CNV@NL17SZ08DFT2G  [SOT353-1-2_125-65-5P]  146.57 27.27 270 top
U13  IT5571E-I-128/CX  [LQFP128-16X16-4-1_6H]  191.05 21.98 270 top
U14  *CNV@NL17SZ08DFT2G  [SOT353-1-2_125-65-5P]  146.47 20.59 270 top
U15  TPM@NPCT750AAAYX  [QFN32-5X5-5-33P-0_85H]  125.69 20.46 90 top
U16  GS@LIS3DHTR  [LGA16-3X3-5]  64.7 17 0 top
U17  HDD_R@SN75LVCP601RTJR  [PWQFN20-4X4-5-26P-0_8H]  210.88 16.37 180 top
U18  *M74VHC1GT08DFT2G  [SC70-2_1-65-5P]  58.99 13.96 270 top
U19  EV@NL17SZ08DFT2G  [SOT353-1-2_125-65-5P]  97.47 123.68 180 bottom
U20  EV@NL17SZ32DFT2G  [SOT353-2_1-65-5P]  101.03 121.14 270 bottom
U21  NS892407  [TRF-N1010G-25P]  32.4 107.58 180 bottom
U22  EV@N17S-G1-A1  [BGA595-NVIDIA-N13P-GV2-S-A2]  105.03 103.73 90 bottom
U23  APL3512ABI-TRG  [SOT23-5-2_8-95-5P-G708]  80.96 98.16 180 bottom
U24  ICL-U 1.2G QPWA  [BGA1526-INTEL-ICL-U]  86.19 57 270 bottom
U25  M74VHC1GT08DFT2G  [SC70-2_1-65-5P]  110.93 52.18 270 bottom
U26  74AUP1G07GW  [SOT353-1-2_125-65-5P]  108.49 48.16 90 bottom
U27  MC74VHC1G08DFT2G  [SOT353-1-2_125-65-5P]  106.03 48.12 90 bottom
U28  G524B2T11U  [SOT23-5-2_8-95-5P-G708]  19.49 44.18 180 bottom
U29  *74AUP1G32SE-7  [SC70-2_1-65-5P]  109.66 36.31 90 bottom
U30  ALC255-CG  [QFN48-6X6-4-49P-ALC280]  204.66 32.63 180 bottom
U31  *APL3512ABI-TRG  [SOT23-2_8-95-5P-EM5213AJ]  106.67 30.39 90 bottom
U32  BIOS SOCKET  [50951-0084N-V01-8P-SOCKET]  162.8 29.91 180 bottom
U33  W25Q64FVSSIQ  [SOIC8-7_9-1_27-2_16H]  162.8 29.91 180 bottom
U34  TPC@PI2EQX632EXUBE_TQFN18  [QFN18-2X2-4-19P-0_4H-SMT]  18.1 22.34 270 bottom
U35  G524B2T11U  [SOT23-5-2_8-95-5P-G708]  206.51 21.27 0 bottom
U36  TPC@TPS25810RVCR(QFN)  [QFN20-4X3-5-27P]  24.7 15.61 270 bottom
VC1  *TVM0G5R5M220R  [C0402]  14.92 85.97 0 top
VRAM1  EV@K4G80325FB-HC28_GDDR5_170P  [BGA170-HYNIX-H5GQ1H24MJR]  133.41 111 0 bottom
VRAM2  EV@K4G80325FB-HC28_GDDR5_170P  [BGA170-HYNIX-H5GQ1H24MJR]  133.41 88.6 180 bottom
Y1  25MHZ/30ppm  [XTL-2_05X1_65-1_4X1_1-0_6H]  44.77 113.12 180 top
Y2  EV@27MHZ/10ppm  [XTL-3_2X2_5-2_2X1_7-0_8H]  100.77 86.85 0 bottom
Y3  32.768KHZ/20ppm  [XTL-3_2X1_5-2_5-SMT]  64.93 35.55 270 bottom
Y4  38.4MHZ/20ppm  [XTL-2X1_6-1_35X1_05]  98.87 25.96 180 bottom

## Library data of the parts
C1 = CAP_POL_BGM: tolerance: CH722RM8811
C2 C5-C8 C13 C14 C44 C76 C103 C506 C509 C522 = CAP_NON-POL_BGM: tolerance: CH6471M9900
C3 C4 C9-C12 C36 C40 C481-C488 = CAP_NON-POL_BGM: tolerance: CH4222K9B04
C15 C47 C55 C59 C60 C71 C73 C75 C83 C85 C87 C100 C101 C111 C140 C152 C156 C161 C165 C168 C171 C204 C213 C224 C235 C461 C465 C479 C494 C496 C497 C499 C500 C514-C517 C519 C550 C573 C574 C581 C646 = CAP_NON-POL_BGM: tolerance: CH6101M9B02
C16 C18 C21 C26 C27 C34 C35 C38 C46 C49 C50 C52 C56 C69 C72 C74 C78-C80 C84 C93 C99 C104 C115 C118 C126 C129 C134 C141 C142 C150 C154 C155 C157 C158 C160 C163 C164 C166 C172 C174 C175 C178 C238 C246 C324 C348 C545 C565 C566 C577 C579 C594 C610 C698 = CAP_NON-POL_BGM: tolerance: CH5101K9B01
C17 = CAP_NON-POL_BGM: tolerance: CH5474K9901
C19 C20 C63 C81 C113 C127 C138 C151 C502 C505 C518 C521 C524 C543 C544 C546-C548 C563 C564 C670 = CAP_NON-POL_BGM: tolerance: CH6221M9900
C22 C24 C25 C28 C29 C39 C42 C43 C45 C51 C53 C54 C58 C64 C65 C68 C88 C90 C94-C96 C106 C114 C116 C117 C128 C133 C139 C180 C181 C222 C272 C277 C304 C349 C351 C380 C382 C454 C463 C493 C495 C501 C508 C530 C531 C533-C538 C542 C551 C578 C586 C593 C603 C604 C606 C609 C668 C669 C673-C675 C682 C684 C695 C700-C702 = CAP_NON-POL_BGM: tolerance: CH4103K1B08
C23 = CAP_NON-POL_BGM: tolerance: CH6101M9905
C30 C31 C41 C48 C57 C66 C70 C77 C82 C86 C89 C98 C102 C107-C110 C135 C143 C503 C504 C507 C510-C513 C520 C523 = CAP_NON-POL_BGM: tolerance: CH5471M9B00
C32 C33 C383 C699 = CAP_NON-POL_BGM: tolerance: CH01506JB06
C37 C600 C605 C607 = CAP_NON-POL_BGM: tolerance: CH21006JB10
C61 = CAP_NON-POL_BGM: tolerance: CH03306JB04
C62 C426 C462 C526 = CAP_NON-POL_BGM: tolerance: CH4104K9B03
C67 C343 C396-C399 C434 = CAP NON-POL_BGM: tolerance: CH21006JB10
C91 C367 C371 C381 C384 C387 C390 C437 C480 C532 C541 = CAP NON-POL_BGM: tolerance: CH11806JB09
C92 C137 = CAP_NON-POL_BGM: tolerance: CH18206KB11
C97 C145 C146 C170 C216 C225 C226 C393 C455 C649 C713 = CAP NON-POL_BGM: tolerance: CH31006KB18
C105 C136 = CAP_NON-POL_BGM: tolerance: CH6221M9B01
C112 = CAP NON-POL_BGM: tolerance: CH41004K910
C119 C121-C124 C144 C148 C149 C162 C167 C173 C184 C191 C193-C195 C199 C202 C207 C215 C227 C228 C232 C233 C251 C252 C257 C260 C261 C266 C267 C274 C278 C281 C303 C312 C314 C316 C317 C320 C321 C330 C338 C339 C341 C342 C346 C354 C359 C435 C575 C584 C588 C589 C591 C592 C595 C596 C598 C633 C662 = CAP NON-POL_BGM: tolerance: CH5101K9B01
C120 C169 C214 C220 C268 C350 C355 C356 C358 C376 C385 C556 C557 C585 C587 C619 C620 C627 C629 C635 C641 C650 C659 C666 C719 EC3 EC4 = CAP NON-POL_BGM: tolerance: CH6101M9B02
C125 = CAP NON-POL_BGM: tolerance: CH3224K1B01
C130 C616 = CAP NON-POL_BGM: tolerance: CH5221M9B02
C131 C189 C258 C259 = CAP NON-POL_BGM: tolerance: CH3474K1B04
C132 C176 C219 = CAP NON-POL_BGM: tolerance: CH-3306TB04
C147 C190 C192 C217 C309 C357 C360 = CAP NON-POL_BGM: tolerance: CH06806JB01
C153 C209 = CAP_NON-POL_BGM: tolerance: CH5222K9B06
C159 C208 C293 C361 C369 C448 C498 C580 C582 C583 C590 C597 = CAP_NON-POL_BGM: tolerance: CH4101K9E01
C177 C221 C223 C230 C231 C241-C243 C245 C254-C256 C271 C286 C288 C290 C292 C294 C299 C305 C307 C458 C459 C710 EC8 = CAP NON-POL_BGM: tolerance: CH6221M9900
C179 C185 C229 C237 C244 C269 C275 C279 C284 C296 C311 C651 = CAP NON-POL_BGM: tolerance: CH6471M9900
C182 C186 C187 C196-C198 C200 C201 C203 C205 C206 C210 C212 C395 C436 C447 C472-C475 C558 C560 = CAP_NON-POL_BGM: tolerance: *
C183 EC9 = CAP_NON-POL_BGM: tolerance: CH12206KB14
C188 C319 C347 C362 C366 C378 C433 C440 C441 C539 C623 C634 C636 C637 C643 C647 C656 C660 C661 C686 C687 C690-C692 = CAP NON-POL_BGM: tolerance: CH4103K1B08
C211 = CAP_NON-POL_BGM: tolerance: CH3224K1B01
C218 C234 C240 C273 C276 C283 C285 C289 C291 C298 C300 C301 C306 C576 = CAP NON-POL_BGM: tolerance: CH0154J0E03
C236 C247 C262 C282 C375 C379 C457 C552 C553 C624 = CAP NON-POL_BGM: tolerance: CH6101M9905
C239 C249 C439 C460 C528 C529 C657 C658 C680 C681 = CAP_NON-POL_BGM: tolerance: CH01006JB08
C248 C250 C253 C263-C265 C297 C302 C308 C313 C315 C325 C331 C335-C337 C602 = CAP NON-POL_BGM: tolerance: CH6102M9B00
C270 C280 C287 C295 C345 C352 C363 C368 = CAP_NON-POL_BGM: tolerance: CH-166B0B00
C310 C608 C672 = CAP_NON-POL_BGM: tolerance: CH14706KB18
C318 C322 = CAP NON-POL_BGM: tolerance: CH22206KB16
C323 C327 C332 C340 C453 C540 C648 = CAP NON-POL_BGM: tolerance: CH11006JB00
C326 C601 = CAP NON-POL_BGM: tolerance: CH0106J0E00
C328 = CAP_NON-POL_BGM: tolerance: CH5102K9B06
C329 C344 C654 = C-0603: tolerance: CH4103K9E01
C333 C334 C714 = CAP NON-POL_BGM: tolerance: CH5471K9E07
C353 C364 C365 C372 C386 C388 C442 C443 C449-C451 C466 C476-C478 C561 C562 C567-C572 C640 C665 C676 C679 C725 C726 = CAP_NON-POL_BGM: tolerance: CH4102K9E00
C370 C489-C491 C611 C613 C644 C645 C677 C678 C707 C712 C715-C718 EC5 = CAP_NON-POL_BGM: tolerance: CH4103K9E01
C373 = CAP_NON-POL_BGM: tolerance: CH02206JB08
C374 C720-C722 = CAP_NON-POL_BGM: tolerance: CH5101K9E02
C377 = CAP NON-POL_BGM: tolerance: CH5102K9B06
C389 = CAP NON-POL_BGM: tolerance: CH01006JB08
C391 C392 C413 C432 C445 C446 C464 C467 C638 C685 C688 C689 C693 C694 C696 C697 C703 = CAP NON-POL_BGM: tolerance: *
C394 C400-C412 C414-C424 C427 = CAP_NON-POL_BGM: tolerance: CH1224K1E00
C425 = CAP NON-POL_BGM: tolerance: CH5223K9901
C428-C431 C468-C471 = CAP_NON-POL_BGM: tolerance: CH3102K1E01
C438 C711 = CAP_NON-POL_BGM: tolerance: CH13906JB16
C444 C452 C492 = CAP NON-POL_BGM: tolerance: CH4104K9B03
C456 C653 = CAP NON-POL_BGM: tolerance: CH5471M9B00
C525 = CAP_NON-POL_BGM: tolerance: CH010GJ0I08
C527 C549 = CAP_NON-POL_BGM: tolerance: CH31006KB18
C554 C555 = CAP NON-POL_BGM: tolerance: CH01206JB05
C559 = CAP NON-POL_BGM: tolerance: CH12206KB14
C599 C612 C671 = CAP_NON-POL_BGM: tolerance: CH7101M9200
C614 C617 C618 C621 C625 C628 C630 C631 = CAP_NON-POL_BGM: tolerance: CH4222M9E01
C615 C622 = CAP_NON-POL_BGM: tolerance: CH5102K1906
C626 C632 = CAP_NON-POL_BGM: tolerance: CH01806JB07
C639 = CAP_NON-POL_BGM: tolerance: CH0106J0E00
C642 C723 C724 = CAP NON-POL_BGM: tolerance: CH4102K9E00
C652 = CAP NON-POL_BGM: tolerance: CH5222K9B06
C655 = CAP_NON-POL_BGM: tolerance: CH5101M9E02
C663 = CAP NON-POL_BGM: tolerance: CH03306JB04
C664 = CAP_NON-POL_BGM: tolerance: CH5102M9E01
C667 = CAP NON-POL_BGM: tolerance: CH02206JB08
C683 = CAP NON-POL_BGM: tolerance: CH7101M9200
C704 C708 = CAP NON-POL_BGM: tolerance: CH6471M9A00
C705 = CAP NON-POL_BGM: tolerance: CH5222K1906
C706 = CAP POL_BGM: tolerance: CH7151M8601
C709 = CAP NON-POL_BGM: tolerance: CH6104K9A00
CN1 = HEADER_4P_50208-00401-V02_BGM: tolerance: DFHD04MR452
CN2 = FFCFPC_40P_BGM: tolerance: DFFC40FR073
CN3 = RJ45_8P_4fix_V3_BGM: tolerance: DFTJ08FR503
CN4 = HDMI_19P_10444-19001_BGM: tolerance: DFHD19MR571
CN5 CN7 = HEADER 4_0: tolerance: DFHS09FRA75
CN6 = FFCFPC_40P_BGM: tolerance: DFFC40FR128
CN8 = FFCFPC_28P_BGM: tolerance: *
CN9 = NGFF_79P_EKEY_NAME_BGM: tolerance: DFHS75FR230
CN10 = FFCFPC_28P_BGM: tolerance: DFFC28FR029
CN11 = FFCFPC_4P_BGM: tolerance: DFHD04MR389
CN12 = FFCFPC_8P_BGM: tolerance: DFFC08FR027
CN13 = FFCFPC_8P_BGM: tolerance: DFFC08FR055
CN14 = USB3_1_24P_8F_V5_BGM: tolerance: DFHS24FR477
CN15 = FFCFPC_18P_BGM: tolerance: *
CN16 = FFCFPC_4P_BGM: tolerance: DFFC04FR100
CN17 = FFCFPC_6P_BGM: tolerance: DFFC06FR198
CN18 = NGFF_79P_MKEY_NAME_BGM: tolerance: DFHS75FR032
CN19 = Header_2P_BGM: tolerance: DFHD02MR073
D1 D34 D35 = DIODE_BGM: tolerance: BC1N4148Z00
D2 D6-D9 D11-D13 D23 D33 D36 D37 D43 = Schottky_DIODE_BGM: tolerance: BCRB500VZ29
D3 D4 D16 D25-D32 = TVS_DIODE_BGM: tolerance: BC0H1BSFZ00
D5 = BAT54A_BGM: tolerance: BCBAT54AZ07
D10 = Varistor_BGM: tolerance: CY000220Z00
D14 D15 = Schottky_DIODE_BGM: tolerance: *
D17 D24 EC6 EC7 = TVS_DIODE_BGM: tolerance: BC005725Z00
D18 D21 D22 = TVS_DIODE_BGM: tolerance: BC03220KZ19
D19 D38 D39 D41 = Varistor_BGM: tolerance: CY00G050B00
D20 = ZENER1 DIODE: tolerance: BDPDZ56BZ07
D40 = ZENER_DIODE_BGM: tolerance: BCAFJ20AZ00
D42 = DIODE SCHOTTKY_1: tolerance: BCBAT54CZ13
EC1 EC2 = CAP_NON-POL_BGM: tolerance: CH1184K1E00
FAN1 = Header_4P_BGM: tolerance: DFHD04MR445
HD1 = FFCFPC_12P_V1_BGM: tolerance: DFFC12FR121
HE1 = HALL_IC_3P_BGM: tolerance: AL008132004
HOLE1-HOLE7 HOLE9 HOLE12-HOLE14 HOLE17 HOLE19-HOLE21 = 3x2_1.1: tolerance: MBZ8P003010
HOLE8 HOLE11 HOLE16 HOLE18 HOLE22 HOLE23 = 3x2_0.1: tolerance: *
HOLE10 HOLE15 = 3x2_1.1: tolerance: MBZAU001010
J1 = OPEN: tolerance: *
JDIM1 = DDR4_DIMM_260P_BGM: tolerance: DFHSR0FR008
L1 L2 L4 L5 L15 L16 = BEAD_BGM: tolerance: CX330T30000
L3 = BEAD_BGM: tolerance: CX301T20000
L6 L9 L10 = BEAD_BGM: tolerance: CX5AG121002
L7 = BEAD_BGM: tolerance: CX000220011
L8 = SHORTPAD_BGM: tolerance: TMPSHT00603
L11 L12 = BEAD_BGM: tolerance: CX5AG601004
L13 = BEAD_BGM: tolerance: CX121T30000
L14 = BEAD_BGM: tolerance: CX08T600000
PC1-PC8 PC10-PC48 PC50 PC52-PC61 PC63-PC133 PC136-PC140 PC142 PC143 PC145-PC149 PC151-PC162 PC167-PC179 PC181-PC185 PC188-PC209 PC212 PC213 PC215-PC217 PC219-PC265 PC267-PC272 = CAP_NON-POL_BGM
PC9 PC134 PC135 PC150 PC164 PC166 PC180 = CAP_POL_BGM
PC49 PC51 PC62 PC141 PC144 PC186 PC187 PC210 PC211 PC214 PC266 = CAP NON-POL_BGM
PC163 PC165 PC218 = CAP POL_BGM
PD1 = Schottky_DIODE_BGM
PD2 PD5 PD6 = ZENER_DIODE_BGM
PD3 = BAT54C_BGM: tolerance: BCBAT54CZ13
PD4 = BAT54C_BGM
PD7 = DIODE_BGM
PJ2-PJ4 PJ7 PJ8 PJ10 PR6-PR8 PR13 PR17-PR20 PR22 PR24-PR26 PR29 PR34-PR38 PR41 PR44-PR46 PR53 PR60-PR63 PR68 PR77 PR80 PR87-PR89 PR91 PR93-PR96 PR99 PR100 PR107 PR109-PR111 PR116 PR117 PR122-PR125 PR127 PR128 PR130 PR147 PR153 PR157 PR184 PR185 PR195 PR215 PR221 PR222 PR227 PR236 PR237 PR242-PR244 PR249-PR251 PR253-PR255 PR257 PR259-PR261 PR267 PR269-PR273 PR276 PR277 = SHORTPAD_V01_BGM
PJ6 = DCJACK_30706-00042-001_BGM
PJ11 = HEADER_8P_2F_BGM
PL1-PL13 = INDUCTOR_BGM_0
PQ1 PQ7 = DTC144EU_BGM
PQ2 PQ5 PQ6 PQ8 PQ9 PQ12 PQ13 PQ15 PQ17 PQ18 PQ23 PQ25 PQ28 = MOS-N_3P_ESD_BGM
PQ3 PQ4 PQ11 PQ19 PQ22 PQ24 PQ26 PQ27 = MOS-N_8P_BGM
PQ10 = MOS-N_3P_BGM
PQ14 PQ16 PQ20 PQ21 = MOS-N-Dual_10P_BGM
PR1 PR3-PR5 PR10 PR11 PR14-PR16 PR21 PR23 PR27 PR28 PR30-PR33 PR39 PR40 PR42 PR43 PR47-PR52 PR54-PR59 PR64-PR67 PR69-PR76 PR78 PR79 PR81-PR86 PR90 PR92 PR97 PR98 PR101-PR106 PR108 PR112-PR115 PR118-PR121 PR126 PR129 PR131 PR132 PR134-PR146 PR148-PR152 PR154-PR156 PR158 PR159 PR162 PR163 PR166-PR181 PR186-PR194 PR196-PR199 PR201-PR210 PR212-PR214 PR216-PR220 PR223-PR225 PR228-PR232 PR234 PR235 PR238-PR241 PR245-PR248 PR252 PR256 PR258 PR262-PR265 PR268 PR274 PR275 PR278 PR279 = RES_BGM
PR2 PR9 PR164 PR165 PR182 PR183 PR200 PR211 PR226 PR233 = SHORTPAD_BGM
PR12 PR266 = R_Current_SEN_BGM
PR133 PR160 PR161 = Thermistor_BGM
PU1 = TPS51486XRJER_18P_BGM
PU2 = RT8813DGQW_BGM
PU3 PU6 PU7 = AOZ1331DI_BGM
PU4 = RT3612EBGQW-02_32P_BGM
PU5 = JW5213DFND_8P_BGM
PU8 = G9336ADJTP1U_BGM
PU9 = G5335QT2U_V1_BGM
PU10 = RT6543BGQW_20P_BGM
PU11 = RT6256BGQUF_12P_BGM
PU12 = BQ24780SRUYR_BGM
PU13 = TMP708_BGM
PU14 = JW5222RSOTB#TRPBF_6P_V1_BGM
PU15 = RT6258CGQUF_12P_BGM
Q1 Q5 Q8 Q9 = MOS-N_3P_ESD_BGM: tolerance: BAM10120003
Q2 = MOS-P_3P_BGM: tolerance: BAM34130001
Q3 Q44 = DTC144EU_BGM: tolerance: BA001440013
Q4 Q17 Q21 Q22 Q24 Q35 Q38-Q41 = MOS-N_Dual_6P_ESD_BGM: tolerance: BAM70020047
Q6 Q10 Q20 Q27 Q30 Q42 = MOS-N_3P_ESD_BGM: tolerance: BAM70020002
Q7 Q31 Q45 = MOS-N_3P_ESD_BGM: tolerance: BAM138K0001
Q11 = NPN_0: tolerance: BA039040020
Q12 = MOS-N_3P_ESD_BGM: tolerance: BAM03010002
Q13 = MOS-N_Dual_6P_ESD_BGM: tolerance: BAM6N430000
Q14 Q36 Q37 = MOS-N_3P_BGM: tolerance: BAM34140000
Q15 = 2N7002_3: tolerance: BAM138K0003
Q16 = NPN_BGM: tolerance: BA039040020
Q18 Q25 Q28 Q29 Q46 = MOS-N_3P_ESD_BGM: tolerance: BAN70020007
Q19 Q47 = MOS-P_3P_BGM: tolerance: BAM21300000
Q23 = MOS-P_8P_BGM: tolerance: BAM20P00001
Q26 = DTA124EU_0: tolerance: BA039060015
Q32 = MOS-N_3P_ESD_BGM_0: tolerance: BAM10120003
Q33 = AP2331SA-7-01_BGM: tolerance: AL002331000
Q34 = MOS-N_3P_ESD_BGM: tolerance: BAM601K0003
Q43 = MOS-N_3P_ESD_BGM: tolerance: BAM01380018
R1 R2 R17 R33 R39 R42 R44 R47 R53 R57 R58 R61-R63 R81 R97-R99 R102 R105 R114 R120 R165 R175 R190 R198 R200 R202 R204 R209 R229 R263 R264 R267 R268 R273 R275 R279 R280 R283 R284 R289 R293 R295 R298 R305 R316 R322 R331 R338 R366 R373 R375 R384 R422 R431 R433 R437 R438 R449 R450 R486 R488 R489 R499 R502 R505 R506 R509 R510 R514 R519-R522 R536 R542 R549 R551 R568 R569 R605 R609 R626 R636 R641 R642 R690 R691 R697 R720 R745 R748 R764 R770 R782 R796 R798 R802 R807 R813 R820 R836 = RES_BGM: tolerance: CS00002JB38
R3 R227 R248 R304 R314 R315 R328 R340 R341 R346 R347 R353 R413 R429 R435 R436 R446 R451 R460 R461 R465 R466 R469-R471 R476 R477 R481 R485 R655 R663 R664 R677 R705 R722 R736 R743 R766 R774 R775 R778 R781 R784 R785 R787 R788 R800 R805 R811 R817 R822-R824 = RES_BGM: tolerance: CS24701JE00
R4 R215 R274 R500 R515 R769 R810 = RES_BGM: tolerance: CS00004JA40
R5 R19 R23 R37 R234 R245 R343 R399 R407 R440 R501 R529 R532 R533 R538-R540 R543 R545-R547 R552 R554 R565-R567 R686 R734 R752 = RES_BGM: tolerance: CS41002JB20
R6 R511 = RES_BGM: tolerance: CS22492FB22
R7 = RES_BGM: tolerance: CS-2204FA00
R8-R11 = RES_BGM: tolerance: CS07504FA11
